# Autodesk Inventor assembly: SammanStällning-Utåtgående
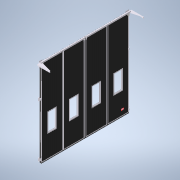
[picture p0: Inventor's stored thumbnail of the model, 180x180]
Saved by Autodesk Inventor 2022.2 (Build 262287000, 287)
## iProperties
Created: 2022-02
Part Number: SammanStällning-Utåtgående
Document SubType Name: Assembly
Designer: cl
Author: cl
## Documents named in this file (19)
- G:\AutoCad\Carl Lund\3D-modeller systemlösningar\3D-modell-systemlösning-2022\SammanStällning-Utåtgående.iam
- G:\AutoCad\Carl Lund\3D-modeller systemlösningar\3D-modell-systemlösning-2022\Parts\BladKomplett2022.iam
- G:\AutoCad\Carl Lund\3D-modeller systemlösningar\3D-modell-systemlösning-2022\Parts\MellanGångjärnH.ipt
- G:\AutoCad\Carl Lund\3D-modeller systemlösningar\3D-modell-systemlösning-2022\Parts\MellanGångjärnV.ipt
- G:\AutoCad\Carl Lund\3D-modeller systemlösningar\3D-modell-systemlösning-2022\Parts\Karmstyrning.ipt
- G:\AutoCad\Carl Lund\3D-modeller systemlösningar\3D-modell-systemlösning-2022\Parts\KarmgångjärnH.ipt
- G:\AutoCad\Carl Lund\3D-modeller systemlösningar\3D-modell-systemlösning-2022\Parts\KarmgångjärnV.ipt
- G:\AutoCad\Carl Lund\3D-modeller systemlösningar\3D-modell-systemlösning-2022\Parts\SidotätningUppe.ipt
- G:\AutoCad\Carl Lund\3D-modeller systemlösningar\3D-modell-systemlösning-2022\Parts\SidoTätning.ipt
- G:\AutoCad\Carl Lund\3D-modeller systemlösningar\3D-modell-systemlösning-2022\Parts\SläpList.ipt
- G:\AutoCad\Carl Lund\3D-modeller systemlösningar\3D-modell-systemlösning-2022\Parts\GummilistMellan.ipt
- G:\AutoCad\Carl Lund\3D-modeller systemlösningar\3D-modell-systemlösning-2022\Styrande.iam
- G:\AutoCad\Carl Lund\3D-modeller systemlösningar\3D-modell-systemlösning-2022\Parts\GarageregelHöger.ipt
- G:\AutoCad\Carl Lund\3D-modeller systemlösningar\3D-modell-systemlösning-2022\Parts\GarageregelVänster.ipt
- G:\AutoCad\Carl Lund\3D-modeller systemlösningar\3D-modell-systemlösning-2022\Parts\styrrulle.ipt
- G:\AutoCad\Carl Lund\3D-modeller systemlösningar\3D-modell-systemlösning-2022\Parts\Styrskena.ipt
- G:\AutoCad\Carl Lund\3D-modeller systemlösningar\3D-modell-systemlösning-2022\Parts\Uppställningsbeslag-H-Ut.ipt
- G:\AutoCad\Carl Lund\3D-modeller systemlösningar\3D-modell-systemlösning-2022\Parts\Uppställningsbeslag-V-Ut.ipt
- G:\AutoCad\Carl Lund\3D-modeller systemlösningar\3D-modell-systemlösning-2022\Parts\Logga.ipt
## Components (44 placed, 17 different names)
1. Logga:1 — Mate:198, Mate:199, Mate:200
2. BladKomplett2022:1 [sub-assembly] — Mate:1, Mate:2, Flush:1, Flush:2, Flush:3, Flush:8, Flush:28, Flush:29, Mate:28, Flush:30, Mate:42, Mate:39, Flush:99, Flush:100, Flush:101, Flush:102, Flush:103, Flush:104, Mate:61, Mate:66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
3. BladKomplett2022:2 [sub-assembly] — Flush:2, Flush:3, Flush:8, Mate:65, Flush:148, Flush:149, Flush:171, Flush:177, Flush:178, Mate:182, Flush:181, Flush:184, Mate:196, Flush:215
4. BladKomplett2022:3 [sub-assembly] — Flush:30, Flush:101, Flush:102, Mate:183, Flush:185, Flush:186, Flush:189, Flush:192
5. BladKomplett2022:4 [sub-assembly] — Flush:32, Flush:100, Flush:103, Mate:64, Flush:146, Flush:147, Mate:184, Flush:193, Flush:194, Flush:197
6. BladKomplett2022:5 [sub-assembly] — Flush:31, Flush:99, Flush:104, Mate:63, Flush:144, Flush:145, Mate:81, Flush:168, Flush:200, Mate:185, Flush:201, Flush:202, Flush:205, Flush:208, Flush:219
7. BladKomplett2022:6 [sub-assembly] — Mate:28, Flush:28, Flush:29, Flush:31, Flush:32, Mate:38, Flush:138, Flush:139, Mate:58, Mate:62, Flush:142, Flush:143, Mate:69, Mate:78, Flush:159, Flush:160, Mate:180, Mate:186, Mate:187, Mate:192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
8. GarageregelHöger:1 — Flush:156, Flush:157, Flush:158
9. GarageregelHöger:2 — Mate:77, Flush:154, Flush:155, Flush:156, Flush:157, Flush:158
10. GarageregelVänster:1 — Flush:161, Flush:162, Flush:163
11. GarageregelVänster:2 — Mate:78, Flush:159, Flush:160, Flush:161, Flush:162, Flush:163
12. Karmstyrning:2 — Mate:38, Flush:138, Mate:186, Flush:209
13. Karmstyrning:3 — Mate:39, Mate:189, Flush:210
14. Karmstyrning:4 — Mate:42, Mate:61, Mate:188, Flush:209
15. KarmgångjärnH:1 — Mate:190, Mate:191, Flush:211, Flush:213, Flush:214
16. KarmgångjärnV:1 — Mate:192, Flush:212, Mate:193, Flush:217, Flush:218
17. Karmstyrning:1 — Flush:139, Mate:58, Mate:187, Flush:210
18. MellanGångjärnH:7 — Flush:177, Flush:178, Mate:182, Flush:179, Flush:180
19. MellanGångjärnH:8 — Flush:179, Flush:180, Flush:181, Flush:182, Flush:183
20. MellanGångjärnH:9 — Flush:182, Flush:183, Flush:184
21. MellanGångjärnV:7 — Mate:183, Flush:185, Flush:186, Flush:187, Flush:188
22. MellanGångjärnV:8 — Flush:187, Flush:188, Flush:189, Flush:190, Flush:191
23. MellanGångjärnV:9 — Flush:190, Flush:191, Flush:192
24. MellanGångjärnH:10 — Flush:198, Flush:199, Flush:200
25. MellanGångjärnH:11 — Flush:195, Flush:196, Flush:197, Flush:198, Flush:199
26. MellanGångjärnH:12 — Mate:184, Flush:193, Flush:194, Flush:195, Flush:196
27. MellanGångjärnV:10 — Mate:185, Flush:201, Flush:202, Flush:203, Flush:204
28. MellanGångjärnV:11 — Flush:203, Flush:204, Flush:205, Flush:206, Flush:207
29. MellanGångjärnV:12 — Flush:206, Flush:207, Flush:208
30. GummilistMellan:2 — Mate:63, Flush:144, Flush:145
31. GummilistMellan:3 — Mate:64, Flush:146, Flush:147
32. GummilistMellan:4 — Mate:65, Flush:148, Flush:149
33. GummilistMellan:5 — Mate:66, Flush:150, Flush:151
34. SidotätningUppe:1 — Mate:68, Mate:178, Flush:176, Mate:179, Mate:181
35. SidoTätning:1 — Mate:69, Mate:76, Mate:180, Mate:181
36. SidoTätning:2 — Mate:72, Mate:177, Mate:179
37. SläpList:1 — Mate:75, Flush:153, Mate:76
38. GummilistMellan:1 — Mate:62, Flush:142, Flush:143
39. Uppställningsbeslag-H-Ut:1 — Flush:213, Flush:214, Mate:194, Mate:195, Flush:216
40. Uppställningsbeslag-V-Ut:1 — Flush:217, Mate:197, Flush:218
41. styrrulle:1 — Mate:81, Flush:168, Flush:219
42. styrrulle:2 — Flush:171, Tangent:1, Mate:196, Flush:215
43. Styrskena:1 — Tangent:1, Flush:174, Mate:176, Flush:175, Mate:195, Flush:216
44. Styrskena:2 — Flush:174, Mate:176, Flush:175
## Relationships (133: Flush 86, Mate 46, Tangent 1)
- Mate:1: BladKomplett2022:1
- Mate:2: BladKomplett2022:1
- Flush:1: BladKomplett2022:1
- Flush:2: BladKomplett2022:1 ↔ BladKomplett2022:2
- Flush:3: BladKomplett2022:1 ↔ BladKomplett2022:2
- Flush:8: BladKomplett2022:1 ↔ BladKomplett2022:2
- Mate:28: BladKomplett2022:1 ↔ BladKomplett2022:6
- Flush:28: BladKomplett2022:1 ↔ BladKomplett2022:6
- Flush:29: BladKomplett2022:1 ↔ BladKomplett2022:6
- Flush:30: BladKomplett2022:1 ↔ BladKomplett2022:3
- Flush:31: BladKomplett2022:5 ↔ BladKomplett2022:6
- Flush:32: BladKomplett2022:4 ↔ BladKomplett2022:6
- Mate:38: BladKomplett2022:6 ↔ Karmstyrning:2
- Mate:39: BladKomplett2022:1 ↔ Karmstyrning:3
- Mate:42: BladKomplett2022:1 ↔ Karmstyrning:4
- Flush:99: BladKomplett2022:1 ↔ BladKomplett2022:5
- Flush:100: BladKomplett2022:1 ↔ BladKomplett2022:4
- Flush:101: BladKomplett2022:1 ↔ BladKomplett2022:3
- Flush:102: BladKomplett2022:1 ↔ BladKomplett2022:3
- Flush:103: BladKomplett2022:1 ↔ BladKomplett2022:4
- Flush:104: BladKomplett2022:1 ↔ BladKomplett2022:5
- Flush:138: BladKomplett2022:6 ↔ Karmstyrning:2
- Flush:139: BladKomplett2022:6 ↔ Karmstyrning:1
- Mate:58: BladKomplett2022:6 ↔ Karmstyrning:1
- Mate:61: BladKomplett2022:1 ↔ Karmstyrning:4
- Mate:62: BladKomplett2022:6 ↔ GummilistMellan:1
- Flush:142: BladKomplett2022:6 ↔ GummilistMellan:1
- Flush:143: BladKomplett2022:6 ↔ GummilistMellan:1
- Mate:63: BladKomplett2022:5 ↔ GummilistMellan:2
- Flush:144: BladKomplett2022:5 ↔ GummilistMellan:2
- Flush:145: BladKomplett2022:5 ↔ GummilistMellan:2
- Mate:64: BladKomplett2022:4 ↔ GummilistMellan:3
- Flush:146: BladKomplett2022:4 ↔ GummilistMellan:3
- Flush:147: BladKomplett2022:4 ↔ GummilistMellan:3
- Mate:65: BladKomplett2022:2 ↔ GummilistMellan:4
- Flush:148: BladKomplett2022:2 ↔ GummilistMellan:4
- Flush:149: BladKomplett2022:2 ↔ GummilistMellan:4
- Mate:66: BladKomplett2022:1 ↔ GummilistMellan:5
- Flush:150: BladKomplett2022:1 ↔ GummilistMellan:5
- Flush:151: BladKomplett2022:1 ↔ GummilistMellan:5
- Mate:68: BladKomplett2022:1 ↔ SidotätningUppe:1
- Mate:69: BladKomplett2022:6 ↔ SidoTätning:1
- Mate:72: BladKomplett2022:1 ↔ SidoTätning:2
- Mate:75: BladKomplett2022:1 ↔ SläpList:1
- Flush:153: BladKomplett2022:1 ↔ SläpList:1
- Mate:76: SidoTätning:1 ↔ SläpList:1
- Mate:77: BladKomplett2022:1 ↔ GarageregelHöger:2
- Flush:154: BladKomplett2022:1 ↔ GarageregelHöger:2
- Flush:155: BladKomplett2022:1 ↔ GarageregelHöger:2
- Flush:156: GarageregelHöger:1 ↔ GarageregelHöger:2
- Flush:157: GarageregelHöger:1 ↔ GarageregelHöger:2
- Flush:158: GarageregelHöger:1 ↔ GarageregelHöger:2
- Mate:78: BladKomplett2022:6 ↔ GarageregelVänster:2
- Flush:159: BladKomplett2022:6 ↔ GarageregelVänster:2
- Flush:160: BladKomplett2022:6 ↔ GarageregelVänster:2
- Flush:161: GarageregelVänster:1 ↔ GarageregelVänster:2
- Flush:162: GarageregelVänster:1 ↔ GarageregelVänster:2
- Flush:163: GarageregelVänster:1 ↔ GarageregelVänster:2
- Mate:81: BladKomplett2022:5 ↔ styrrulle:1
- Flush:168: BladKomplett2022:5 ↔ styrrulle:1
- Flush:171: BladKomplett2022:2 ↔ styrrulle:2
- Tangent:1: styrrulle:2 ↔ Styrskena:1
- Flush:174: Styrskena:1 ↔ Styrskena:2
- Mate:176: Styrskena:1 ↔ Styrskena:2
- Flush:175: Styrskena:1 ↔ Styrskena:2
- Mate:177: BladKomplett2022:1 ↔ SidoTätning:2
- Mate:178: BladKomplett2022:1 ↔ SidotätningUppe:1
- Flush:176: BladKomplett2022:1 ↔ SidotätningUppe:1
- Mate:179: SidotätningUppe:1 ↔ SidoTätning:2
- Mate:180: BladKomplett2022:6 ↔ SidoTätning:1
- Mate:181: SidotätningUppe:1 ↔ SidoTätning:1
- Flush:177: BladKomplett2022:2 ↔ MellanGångjärnH:7
- Flush:178: BladKomplett2022:2 ↔ MellanGångjärnH:7
- Mate:182: BladKomplett2022:2 ↔ MellanGångjärnH:7
- Flush:179: MellanGångjärnH:7 ↔ MellanGångjärnH:8
- Flush:180: MellanGångjärnH:7 ↔ MellanGångjärnH:8
- Flush:181: BladKomplett2022:2 ↔ MellanGångjärnH:8
- Flush:182: MellanGångjärnH:8 ↔ MellanGångjärnH:9
- Flush:183: MellanGångjärnH:8 ↔ MellanGångjärnH:9
- Flush:184: BladKomplett2022:2 ↔ MellanGångjärnH:9
- Mate:183: BladKomplett2022:3 ↔ MellanGångjärnV:7
- Flush:185: BladKomplett2022:3 ↔ MellanGångjärnV:7
- Flush:186: BladKomplett2022:3 ↔ MellanGångjärnV:7
- Flush:187: MellanGångjärnV:7 ↔ MellanGångjärnV:8
- Flush:188: MellanGångjärnV:7 ↔ MellanGångjärnV:8
- Flush:189: BladKomplett2022:3 ↔ MellanGångjärnV:8
- Flush:190: MellanGångjärnV:8 ↔ MellanGångjärnV:9
- Flush:191: MellanGångjärnV:8 ↔ MellanGångjärnV:9
- Flush:192: BladKomplett2022:3 ↔ MellanGångjärnV:9
- Mate:184: BladKomplett2022:4 ↔ MellanGångjärnH:12
- Flush:193: BladKomplett2022:4 ↔ MellanGångjärnH:12
- Flush:194: BladKomplett2022:4 ↔ MellanGångjärnH:12
- Flush:195: MellanGångjärnH:11 ↔ MellanGångjärnH:12
- Flush:196: MellanGångjärnH:11 ↔ MellanGångjärnH:12
- Flush:197: BladKomplett2022:4 ↔ MellanGångjärnH:11
- Flush:198: MellanGångjärnH:10 ↔ MellanGångjärnH:11
- Flush:199: MellanGångjärnH:10 ↔ MellanGångjärnH:11
- Flush:200: BladKomplett2022:5 ↔ MellanGångjärnH:10
- Mate:185: BladKomplett2022:5 ↔ MellanGångjärnV:10
- Flush:201: BladKomplett2022:5 ↔ MellanGångjärnV:10
- Flush:202: BladKomplett2022:5 ↔ MellanGångjärnV:10
- Flush:203: MellanGångjärnV:10 ↔ MellanGångjärnV:11
- Flush:204: MellanGångjärnV:10 ↔ MellanGångjärnV:11
- Flush:205: BladKomplett2022:5 ↔ MellanGångjärnV:11
- Flush:206: MellanGångjärnV:11 ↔ MellanGångjärnV:12
- Flush:207: MellanGångjärnV:11 ↔ MellanGångjärnV:12
- Flush:208: BladKomplett2022:5 ↔ MellanGångjärnV:12
- Mate:186: BladKomplett2022:6 ↔ Karmstyrning:2
- Mate:187: BladKomplett2022:6 ↔ Karmstyrning:1
- Mate:188: BladKomplett2022:1 ↔ Karmstyrning:4
- Flush:209: Karmstyrning:2 ↔ Karmstyrning:4
- Mate:189: BladKomplett2022:1 ↔ Karmstyrning:3
- Flush:210: Karmstyrning:3 ↔ Karmstyrning:1
- Mate:190: BladKomplett2022:1 ↔ KarmgångjärnH:1
- Mate:191: BladKomplett2022:1 ↔ KarmgångjärnH:1
- Flush:211: BladKomplett2022:1 ↔ KarmgångjärnH:1
- Mate:192: BladKomplett2022:6 ↔ KarmgångjärnV:1
- Flush:212: BladKomplett2022:6 ↔ KarmgångjärnV:1
- Mate:193: BladKomplett2022:6 ↔ KarmgångjärnV:1
- Flush:213: KarmgångjärnH:1 ↔ Uppställningsbeslag-H-Ut:1
- Flush:214: KarmgångjärnH:1 ↔ Uppställningsbeslag-H-Ut:1
- Mate:194: BladKomplett2022:1 ↔ Uppställningsbeslag-H-Ut:1
- Mate:195: Uppställningsbeslag-H-Ut:1 ↔ Styrskena:1
- Mate:196: BladKomplett2022:2 ↔ styrrulle:2
- Flush:215: BladKomplett2022:2 ↔ styrrulle:2
- Flush:216: Uppställningsbeslag-H-Ut:1 ↔ Styrskena:1
- Flush:217: KarmgångjärnV:1 ↔ Uppställningsbeslag-V-Ut:1
- Mate:197: BladKomplett2022:6 ↔ Uppställningsbeslag-V-Ut:1
- Flush:218: KarmgångjärnV:1 ↔ Uppställningsbeslag-V-Ut:1
- Flush:219: BladKomplett2022:5 ↔ styrrulle:1
- Mate:198: Logga:1 ↔ BladKomplett2022:6
- Mate:199: Logga:1 ↔ BladKomplett2022:6
- Mate:200: Logga:1 ↔ BladKomplett2022:6
## Named parameters: Blad2 = 1012.5 mm, Blad3 = 0, Blad4 = 0, Blad5 = 1012.5 mm, MGJ12Djup = 0, MGJ12Bredd = 0, MGJ56Djup = 0, MGJ56Bredd = 0, MGJ23Djup = 48 mm, MGJ45Djup = 48 mm, GarageRegel5 = 0, GarageRegel6 = 0, BladBredd = 987.5 mm, Fönsterhöjd = 862 mm, Blad2_1 = 1012.5 mm, Blad3_1 = 0, Blad4_1 = 0, Blad5_1 = 1012.5 mm, Blad6 = 2025 mm, MGJ12Djup_1 = 0, MGJ12Bredd_1 = 0, MGJ2Djup = 0, MGJ2Bredd = 5012.5 mm, MGJ56Djup_1 = 0, MGJ56Bredd_1 = 0, MGJ23Djup_1 = 48 mm, MGJ45Djup_1 = 48 mm, GarageRegel5_1 = 0, GarageRegel6_1 = 0, Styrrulle2Djup = 0
